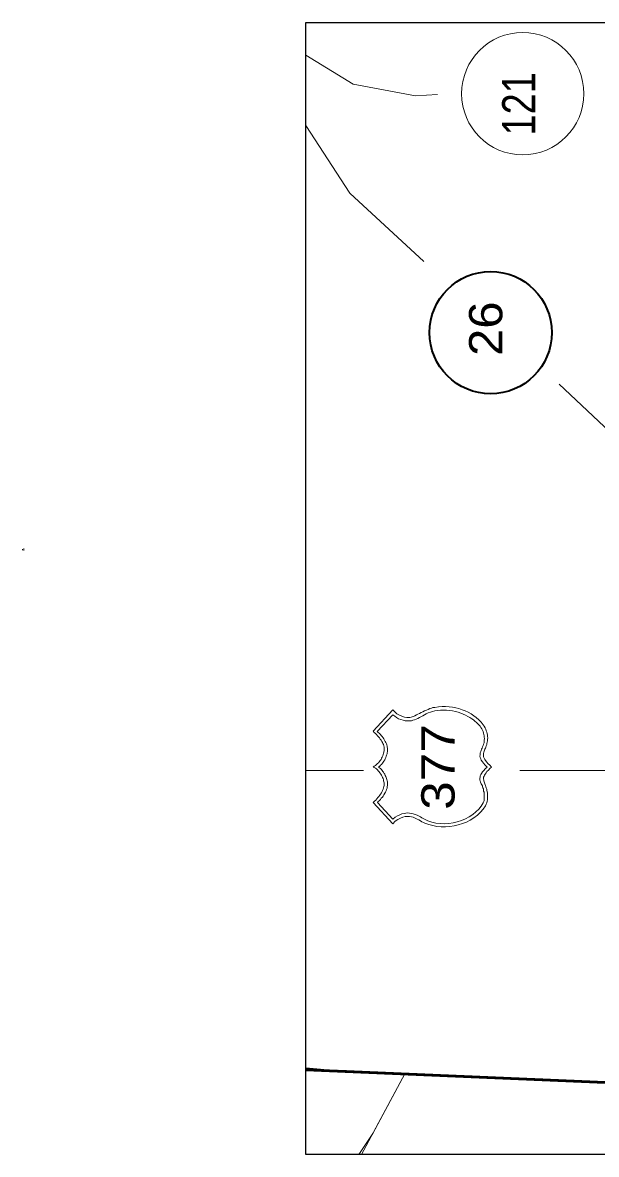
# Model space of a CAD drawing. Extents: x 2363323 to 2367082, y 6956018 to 6980837.
# Drawn here: x 2365163 to 2365427, y 6956018 to 6956538 of the extents above; entities that cross this region are included whole.
import ezdxf

# ---------------------------------------------------------------- set-up
doc = ezdxf.new("R2010")
doc.units = 0
doc.header["$LTSCALE"] = 4.1
for name, color, linetype, lineweight in [('61', 7, 'Continuous', 40), ('62', 7, 'Continuous', 13), ('63', 7, 'Continuous', 13)]:
    doc.layers.add(name, color=color, linetype=linetype, lineweight=lineweight)

msp = doc.modelspace()

# ---------------------------------------------------------------- linework, layer by layer
at = {"layer": '61', "lineweight": 25}
msp.add_lwpolyline([(2365293.134, 6956018.485), (2365293.134, 6956538.196), (2365958.89, 6956538.196), (2365958.89, 6956018.485)], close=True, dxfattribs=at)
at = {"layer": '62'}
for p, q in [((2365343.609, 6956504.644), (2365353.697, 6956505.184)), ((2365293.134, 6956490.977), (2365313.365, 6956459.916)), ((2365313.365, 6956459.916), (2365347.481, 6956428.58)), ((2365446.841, 6956337.136), (2365409.581, 6956372.152)), ((2365163.018, 6956296.007), (2365163.019, 6956296.479)), ((2365163.648, 6956295.715), (2365163.649, 6956296.749)), ((2365319.657, 6956194.836), (2365293.137, 6956194.836)), ((2365566.921, 6956194.836), (2365391.497, 6956194.836)), ((2365318.801, 6956018.484), (2365338.665, 6956055.412)), ((2365317.489, 6956018.484), (2365323.993, 6956028.136))]:
    msp.add_line(p, q, dxfattribs=at)
at = {"layer": '62', "lineweight": 25}
msp.add_line((2365308.229, 6956056.672), (2365293.137, 6956058.008), dxfattribs=at)
at = {"layer": '62'}
for points in [[(2365343.609, 6956504.644), (2365314.977, 6956509.956), (2365293.137, 6956523.332)], [(2365333.16, 6956170.305), (2365324.106, 6956180.094), (2365324.715, 6956180.634), (2365325.327, 6956181.171), (2365325.798, 6956181.783), (2365326.338, 6956182.323), (2365326.749, 6956182.863), (2365327.151, 6956183.475), (2365327.553, 6956183.946), (2365327.958, 6956184.555), (2365328.3, 6956185.095), (2365328.498, 6956185.635), (2365328.771, 6956186.241), (2365328.909, 6956186.781), (2365329.11, 6956187.387), (2365329.245, 6956187.861), (2365329.245, 6956188.473), (2365329.179, 6956189.076), (2365329.107, 6956189.487), (2365328.909, 6956189.955), (2365328.837, 6956190.495), (2365328.699, 6956191.035), (2365328.429, 6956191.575), (2365328.228, 6956192.046), (2365327.958, 6956192.586), (2365327.688, 6956193.129), (2365327.283, 6956193.666), (2365326.947, 6956194.137), (2365326.473, 6956194.611), (2365326.209, 6956195.088), (2365325.669, 6956195.487), (2365325.186, 6956195.826), (2365324.646, 6956196.096), (2365324.109, 6956196.369), (2365324.646, 6956196.708), (2365325.186, 6956197.107), (2365325.735, 6956197.446), (2365326.203, 6956197.917), (2365326.677, 6956198.319), (2365327.013, 6956198.868), (2365327.418, 6956199.336), (2365327.76, 6956199.879), (2365328.021, 6956200.416), (2365328.363, 6956200.956), (2365328.567, 6956201.565), (2365328.771, 6956202.105), (2365328.903, 6956202.783), (2365329.107, 6956203.257), (2365329.245, 6956203.929), (2365329.245, 6956204.538), (2365329.245, 6956205.006), (2365329.245, 6956205.546), (2365329.041, 6956206.017), (2365328.903, 6956206.626), (2365328.627, 6956207.097), (2365328.429, 6956207.643), (2365328.093, 6956208.117), (2365327.823, 6956208.651), (2365327.418, 6956209.128), (2365327.013, 6956209.737), (2365326.608, 6956210.208), (2365326.203, 6956210.748), (2365325.663, 6956211.219), (2365325.186, 6956211.828), (2365324.649, 6956212.227), (2365324.109, 6956212.773), (2365333.16, 6956222.565), (2365334.042, 6956221.683), (2365335.053, 6956220.807), (2365336.199, 6956220.198), (2365337.351, 6956219.727), (2365338.491, 6956219.253), (2365339.571, 6956219.118), (2365340.45, 6956219.049), (2365341.059, 6956219.118), (2365341.599, 6956219.19), (2365342.142, 6956219.457), (2365342.745, 6956219.589), (2365343.351, 6956219.928), (2365344.032, 6956220.267), (2365344.701, 6956220.603), (2365345.451, 6956220.939), (2365346.261, 6956221.347), (2365347.002, 6956221.749), (2365347.74, 6956222.151), (2365348.619, 6956222.493), (2365349.36, 6956222.829), (2365350.17, 6956223.168), (2365350.911, 6956223.375), (2365351.655, 6956223.639), (2365352.465, 6956223.705), (2365354.157, 6956223.975), (2365355.84, 6956224.113), (2365357.391, 6956224.113), (2365359.011, 6956223.978), (2365360.571, 6956223.843), (2365362.119, 6956223.507), (2365363.601, 6956223.168), (2365365.092, 6956222.697), (2365366.505, 6956222.157), (2365367.861, 6956221.479)], [(2365370.222, 6956217.969), (2365369.475, 6956218.509), (2365368.602, 6956219.118), (2365367.651, 6956219.589), (2365366.64, 6956220.129), (2365365.56, 6956220.609), (2365364.417, 6956221.077), (2365363.202, 6956221.548), (2365361.987, 6956221.887), (2365360.631, 6956222.16), (2365359.281, 6956222.358), (2365357.931, 6956222.493), (2365356.515, 6956222.493), (2365355.03, 6956222.43), (2365353.752, 6956222.289), (2365352.537, 6956222.157), (2365351.451, 6956221.887), (2365350.443, 6956221.548), (2365349.495, 6956221.209), (2365348.55, 6956220.807), (2365347.74, 6956220.399), (2365346.93, 6956219.928), (2365346.123, 6956219.46), (2365345.382, 6956219.118), (2365344.641, 6956218.713), (2365343.897, 6956218.377), (2365343.15, 6956218.038), (2365342.409, 6956217.837), (2365341.737, 6956217.633), (2365340.927, 6956217.501), (2365339.979, 6956217.498), (2365338.899, 6956217.639), (2365337.885, 6956217.837), (2365336.871, 6956218.11), (2365335.863, 6956218.509), (2365334.921, 6956219.118), (2365334.042, 6956219.727), (2365333.16, 6956220.399), (2365326.005, 6956212.71), (2365326.473, 6956212.227), (2365326.947, 6956211.831), (2365327.487, 6956211.357), (2365327.889, 6956210.883), (2365328.297, 6956210.343), (2365328.705, 6956209.803), (2365329.038, 6956209.263), (2365329.38, 6956208.717), (2365329.653, 6956208.111), (2365329.989, 6956207.571), (2365330.262, 6956206.965), (2365330.391, 6956206.491), (2365330.532, 6956205.885), (2365330.601, 6956205.411), (2365330.73, 6956205.006), (2365330.73, 6956204.529), (2365330.73, 6956204.061), (2365330.667, 6956203.455), (2365330.595, 6956202.915), (2365330.529, 6956202.375), (2365330.325, 6956201.766), (2365330.121, 6956201.298), (2365329.923, 6956200.686), (2365329.653, 6956200.149), (2365329.449, 6956199.675), (2365329.11, 6956198.997), (2365328.771, 6956198.598), (2365328.429, 6956198.121), (2365328.027, 6956197.587), (2365327.553, 6956197.248), (2365327.151, 6956196.771), (2365326.545, 6956196.363), (2365327.079, 6956195.955), (2365327.553, 6956195.625), (2365327.958, 6956195.151), (2365328.297, 6956194.746), (2365328.633, 6956194.347), (2365328.903, 6956193.939), (2365329.245, 6956193.396), (2365329.581, 6956193.057), (2365329.722, 6956192.517), (2365329.989, 6956192.046), (2365330.121, 6956191.578), (2365330.331, 6956191.107), (2365330.391, 6956190.624), (2365330.601, 6956190.087), (2365330.667, 6956189.613), (2365330.73, 6956189.145), (2365330.799, 6956188.605), (2365330.802, 6956187.927), (2365330.661, 6956187.384), (2365330.529, 6956186.715), (2365330.325, 6956186.106), (2365330.055, 6956185.431), (2365329.791, 6956184.756), (2365329.452, 6956184.285), (2365329.107, 6956183.607), (2365328.771, 6956183.001), (2365328.369, 6956182.452), (2365327.895, 6956181.984), (2365327.49, 6956181.375), (2365326.95, 6956180.904)], [(2365367.861, 6956221.479), (2365369.142, 6956220.738), (2365370.357, 6956219.928), (2365371.569, 6956219.049), (2365372.721, 6956217.966), (2365373.729, 6956216.889), (2365374.74, 6956215.743), (2365375.217, 6956215.068), (2365375.619, 6956214.399), (2365375.955, 6956213.718), (2365376.162, 6956213.043), (2365376.429, 6956212.437), (2365376.567, 6956211.759), (2365376.699, 6956211.018), (2365376.771, 6956210.409), (2365376.831, 6956209.74), (2365376.765, 6956209.065), (2365376.765, 6956208.447), (2365376.63, 6956207.841), (2365376.429, 6956207.166), (2365376.363, 6956206.626), (2365376.162, 6956206.086), (2365375.955, 6956205.549), (2365375.751, 6956205.006), (2365375.553, 6956204.535), (2365375.28, 6956204.061), (2365375.145, 6956203.593), (2365375.01, 6956203.116), (2365374.875, 6956202.576), (2365374.809, 6956202.108), (2365374.809, 6956201.565), (2365374.941, 6956201.028), (2365375.145, 6956200.485), (2365375.481, 6956199.876), (2365375.823, 6956199.336), (2365376.363, 6956198.595), (2365376.9, 6956197.917), (2365377.713, 6956197.245), (2365378.589, 6956196.366), (2365377.779, 6956195.628), (2365377.101, 6956194.881), (2365376.429, 6956194.275), (2365376.021, 6956193.666), (2365375.619, 6956193.129), (2365375.283, 6956192.583), (2365375.145, 6956192.115), (2365374.941, 6956191.641), (2365374.881, 6956191.236), (2365374.881, 6956190.768), (2365374.947, 6956190.426), (2365375.079, 6956189.955), (2365375.151, 6956189.547), (2365375.28, 6956189.145), (2365375.481, 6956188.671), (2365375.619, 6956188.203), (2365375.823, 6956187.861), (2365375.961, 6956187.321), (2365376.159, 6956186.781), (2365376.36, 6956186.241), (2365376.429, 6956185.635), (2365376.567, 6956185.095), (2365376.699, 6956184.423), (2365376.771, 6956183.883), (2365376.771, 6956183.199), (2365376.771, 6956182.665), (2365376.765, 6956181.984), (2365376.702, 6956181.246), (2365376.501, 6956180.637), (2365376.36, 6956179.965), (2365376.093, 6956179.287), (2365375.751, 6956178.609), (2365374.74, 6956177.055), (2365373.453, 6956175.573), (2365372.04, 6956174.223), (2365370.492, 6956173.011), (2365368.8, 6956171.925), (2365367.111, 6956171.055), (2365365.227, 6956170.374), (2365363.265, 6956169.771), (2365361.381, 6956169.363), (2365359.419, 6956169.024), (2365357.391, 6956168.889), (2365355.435, 6956168.889), (2365353.41, 6956169.093), (2365351.589, 6956169.435), (2365349.693, 6956169.969), (2365347.941, 6956170.644), (2365347.272, 6956170.914), (2365346.591, 6956171.253), (2365345.853, 6956171.655), (2365345.112, 6956172.129), (2365344.302, 6956172.471), (2365343.489, 6956172.873), (2365342.61, 6956173.275), (2365341.731, 6956173.413), (2365340.792, 6956173.614), (2365339.775, 6956173.614), (2365338.833, 6956173.614), (2365337.753, 6956173.275), (2365336.67, 6956172.939), (2365335.461, 6956172.267)], [(2365326.068, 6956180.094), (2365333.16, 6956172.405), (2365334.312, 6956173.275), (2365335.392, 6956173.881), (2365336.403, 6956174.424), (2365337.345, 6956174.829), (2365338.362, 6956175.036), (2365339.235, 6956175.231), (2365340.045, 6956175.369), (2365340.921, 6956175.237), (2365341.8, 6956175.033), (2365342.61, 6956174.895), (2365343.492, 6956174.625), (2365344.302, 6956174.223), (2365345.043, 6956173.884), (2365345.85, 6956173.479), (2365346.591, 6956173.005), (2365347.401, 6956172.534), (2365349.225, 6956171.655), (2365351.121, 6956171.049), (2365352.939, 6956170.575), (2365354.901, 6956170.377), (2365356.92, 6956170.305), (2365358.951, 6956170.374), (2365360.907, 6956170.713), (2365362.788, 6956171.184), (2365364.75, 6956171.793), (2365366.571, 6956172.606), (2365368.332, 6956173.479), (2365369.952, 6956174.559), (2365371.299, 6956175.705), (2365372.715, 6956176.989), (2365373.795, 6956178.405), (2365374.74, 6956179.893), (2365374.809, 6956180.235), (2365375.01, 6956180.571), (2365375.145, 6956181.039), (2365375.145, 6956181.579), (2365375.145, 6956181.987), (2365375.211, 6956182.527), (2365375.211, 6956183.064), (2365375.145, 6956183.607), (2365375.145, 6956184.216), (2365375.145, 6956184.756), (2365374.941, 6956185.299), (2365374.875, 6956185.839), (2365374.809, 6956186.379), (2365374.605, 6956186.847), (2365374.47, 6956187.315), (2365374.341, 6956187.729), (2365374.065, 6956188.203), (2365373.867, 6956188.605), (2365373.66, 6956189.007), (2365373.531, 6956189.415), (2365373.321, 6956189.958), (2365373.255, 6956190.291), (2365373.192, 6956190.765), (2365373.189, 6956191.236), (2365373.261, 6956191.704), (2365373.39, 6956192.385), (2365373.591, 6956192.856), (2365373.999, 6956193.396), (2365374.335, 6956194.077), (2365375.01, 6956194.746), (2365375.685, 6956195.556), (2365376.567, 6956196.303), (2365375.622, 6956197.245), (2365374.941, 6956198.055), (2365374.335, 6956198.727), (2365373.867, 6956199.477), (2365373.597, 6956200.146), (2365373.39, 6956200.686), (2365373.255, 6956201.298), (2365373.261, 6956201.901), (2365373.321, 6956202.441), (2365373.39, 6956202.915), (2365373.597, 6956203.455), (2365373.795, 6956203.989), (2365373.993, 6956204.535), (2365374.269, 6956205.006), (2365374.473, 6956205.615), (2365374.743, 6956206.221), (2365374.875, 6956206.827), (2365375.151, 6956207.439), (2365375.151, 6956208.111), (2365375.217, 6956208.717), (2365375.28, 6956209.398), (2365375.217, 6956210.073), (2365375.151, 6956210.679), (2365375.079, 6956211.357), (2365374.881, 6956211.963), (2365374.74, 6956212.638), (2365374.335, 6956213.241), (2365374.065, 6956213.925), (2365373.66, 6956214.459), (2365373.261, 6956215.137), (2365372.721, 6956215.743), (2365372.175, 6956216.349), (2365371.635, 6956216.823), (2365370.888, 6956217.363), (2365370.222, 6956217.969)], [(2365326.95, 6956180.904), (2365326.473, 6956180.499), (2365326.068, 6956180.094)], [(2365335.461, 6956172.267), (2365334.309, 6956171.454), (2365333.16, 6956170.305)]]:
    msp.add_lwpolyline(points, dxfattribs=at)
at = {"layer": '62', "lineweight": 53}
msp.add_lwpolyline([(2365293.137, 6956057.312), (2365488.705, 6956049.028), (2365530.289, 6956056.396)], dxfattribs=at)
at = {"layer": '62'}
msp.add_circle((2365392.892, 6956505.564), 28.094, dxfattribs=at)
at = {"layer": '62', "lineweight": 35}
msp.add_circle((2365378.16, 6956395.847), 28.094, dxfattribs=at)
at = {"layer": '63'}
for p, q in [((2365343.609, 6956504.644), (2365314.977, 6956509.956)), ((2365343.609, 6956504.644), (2365353.697, 6956505.184)), ((2365313.365, 6956459.916), (2365347.481, 6956428.58)), ((2365446.841, 6956337.136), (2365409.581, 6956372.152)), ((2365163.018, 6956296.007), (2365163.019, 6956296.479)), ((2365163.648, 6956295.715), (2365163.649, 6956296.749)), ((2365319.657, 6956194.836), (2365293.137, 6956194.836)), ((2365566.921, 6956194.836), (2365391.497, 6956194.836))]:
    msp.add_line(p, q, dxfattribs=at)
at = {"layer": '63', "lineweight": 25}
msp.add_line((2365308.229, 6956056.672), (2365293.137, 6956058.008), dxfattribs=at)
at = {"layer": '63'}
for points in [[(2365333.16, 6956170.305), (2365324.106, 6956180.094), (2365324.715, 6956180.634), (2365325.327, 6956181.171), (2365325.798, 6956181.783), (2365326.338, 6956182.323), (2365326.749, 6956182.863), (2365327.151, 6956183.475), (2365327.553, 6956183.946), (2365327.958, 6956184.555), (2365328.3, 6956185.095), (2365328.498, 6956185.635), (2365328.771, 6956186.241), (2365328.909, 6956186.781), (2365329.11, 6956187.387), (2365329.245, 6956187.861), (2365329.245, 6956188.473), (2365329.179, 6956189.076), (2365329.107, 6956189.487), (2365328.909, 6956189.955), (2365328.837, 6956190.495), (2365328.699, 6956191.035), (2365328.429, 6956191.575), (2365328.228, 6956192.046), (2365327.958, 6956192.586), (2365327.688, 6956193.129), (2365327.283, 6956193.666), (2365326.947, 6956194.137), (2365326.473, 6956194.611), (2365326.209, 6956195.088), (2365325.669, 6956195.487), (2365325.186, 6956195.826), (2365324.646, 6956196.096), (2365324.109, 6956196.369), (2365324.646, 6956196.708), (2365325.186, 6956197.107), (2365325.735, 6956197.446), (2365326.203, 6956197.917), (2365326.677, 6956198.319), (2365327.013, 6956198.868), (2365327.418, 6956199.336), (2365327.76, 6956199.879), (2365328.021, 6956200.416), (2365328.363, 6956200.956), (2365328.567, 6956201.565), (2365328.771, 6956202.105), (2365328.903, 6956202.783), (2365329.107, 6956203.257), (2365329.245, 6956203.929), (2365329.245, 6956204.538), (2365329.245, 6956205.006), (2365329.245, 6956205.546), (2365329.041, 6956206.017), (2365328.903, 6956206.626), (2365328.627, 6956207.097), (2365328.429, 6956207.643), (2365328.093, 6956208.117), (2365327.823, 6956208.651), (2365327.418, 6956209.128), (2365327.013, 6956209.737), (2365326.608, 6956210.208), (2365326.203, 6956210.748), (2365325.663, 6956211.219), (2365325.186, 6956211.828), (2365324.649, 6956212.227), (2365324.109, 6956212.773), (2365333.16, 6956222.565), (2365334.042, 6956221.683), (2365335.053, 6956220.807), (2365336.199, 6956220.198), (2365337.351, 6956219.727), (2365338.491, 6956219.253), (2365339.571, 6956219.118), (2365340.45, 6956219.049), (2365341.059, 6956219.118), (2365341.599, 6956219.19), (2365342.142, 6956219.457), (2365342.745, 6956219.589), (2365343.351, 6956219.928), (2365344.032, 6956220.267), (2365344.701, 6956220.603), (2365345.451, 6956220.939), (2365346.261, 6956221.347), (2365347.002, 6956221.749), (2365347.74, 6956222.151), (2365348.619, 6956222.493), (2365349.36, 6956222.829), (2365350.17, 6956223.168), (2365350.911, 6956223.375), (2365351.655, 6956223.639), (2365352.465, 6956223.705), (2365354.157, 6956223.975), (2365355.84, 6956224.113), (2365357.391, 6956224.113), (2365359.011, 6956223.978), (2365360.571, 6956223.843), (2365362.119, 6956223.507), (2365363.601, 6956223.168), (2365365.092, 6956222.697), (2365366.505, 6956222.157), (2365367.861, 6956221.479)], [(2365370.222, 6956217.969), (2365369.475, 6956218.509), (2365368.602, 6956219.118), (2365367.651, 6956219.589), (2365366.64, 6956220.129), (2365365.56, 6956220.609), (2365364.417, 6956221.077), (2365363.202, 6956221.548), (2365361.987, 6956221.887), (2365360.631, 6956222.16), (2365359.281, 6956222.358), (2365357.931, 6956222.493), (2365356.515, 6956222.493), (2365355.03, 6956222.43), (2365353.752, 6956222.289), (2365352.537, 6956222.157), (2365351.451, 6956221.887), (2365350.443, 6956221.548), (2365349.495, 6956221.209), (2365348.55, 6956220.807), (2365347.74, 6956220.399), (2365346.93, 6956219.928), (2365346.123, 6956219.46), (2365345.382, 6956219.118), (2365344.641, 6956218.713), (2365343.897, 6956218.377), (2365343.15, 6956218.038), (2365342.409, 6956217.837), (2365341.737, 6956217.633), (2365340.927, 6956217.501), (2365339.979, 6956217.498), (2365338.899, 6956217.639), (2365337.885, 6956217.837), (2365336.871, 6956218.11), (2365335.863, 6956218.509), (2365334.921, 6956219.118), (2365334.042, 6956219.727), (2365333.16, 6956220.399), (2365326.005, 6956212.71), (2365326.473, 6956212.227), (2365326.947, 6956211.831), (2365327.487, 6956211.357), (2365327.889, 6956210.883), (2365328.297, 6956210.343), (2365328.705, 6956209.803), (2365329.038, 6956209.263), (2365329.38, 6956208.717), (2365329.653, 6956208.111), (2365329.989, 6956207.571), (2365330.262, 6956206.965), (2365330.391, 6956206.491), (2365330.532, 6956205.885), (2365330.601, 6956205.411), (2365330.73, 6956205.006), (2365330.73, 6956204.529), (2365330.73, 6956204.061), (2365330.667, 6956203.455), (2365330.595, 6956202.915), (2365330.529, 6956202.375), (2365330.325, 6956201.766), (2365330.121, 6956201.298), (2365329.923, 6956200.686), (2365329.653, 6956200.149), (2365329.449, 6956199.675), (2365329.11, 6956198.997), (2365328.771, 6956198.598), (2365328.429, 6956198.121), (2365328.027, 6956197.587), (2365327.553, 6956197.248), (2365327.151, 6956196.771), (2365326.545, 6956196.363), (2365327.079, 6956195.955), (2365327.553, 6956195.625), (2365327.958, 6956195.151), (2365328.297, 6956194.746), (2365328.633, 6956194.347), (2365328.903, 6956193.939), (2365329.245, 6956193.396), (2365329.581, 6956193.057), (2365329.722, 6956192.517), (2365329.989, 6956192.046), (2365330.121, 6956191.578), (2365330.331, 6956191.107), (2365330.391, 6956190.624), (2365330.601, 6956190.087), (2365330.667, 6956189.613), (2365330.73, 6956189.145), (2365330.799, 6956188.605), (2365330.802, 6956187.927), (2365330.661, 6956187.384), (2365330.529, 6956186.715), (2365330.325, 6956186.106), (2365330.055, 6956185.431), (2365329.791, 6956184.756), (2365329.452, 6956184.285), (2365329.107, 6956183.607), (2365328.771, 6956183.001), (2365328.369, 6956182.452), (2365327.895, 6956181.984), (2365327.49, 6956181.375), (2365326.95, 6956180.904)], [(2365367.861, 6956221.479), (2365369.142, 6956220.738), (2365370.357, 6956219.928), (2365371.569, 6956219.049), (2365372.721, 6956217.966), (2365373.729, 6956216.889), (2365374.74, 6956215.743), (2365375.217, 6956215.068), (2365375.619, 6956214.399), (2365375.955, 6956213.718), (2365376.162, 6956213.043), (2365376.429, 6956212.437), (2365376.567, 6956211.759), (2365376.699, 6956211.018), (2365376.771, 6956210.409), (2365376.831, 6956209.74), (2365376.765, 6956209.065), (2365376.765, 6956208.447), (2365376.63, 6956207.841), (2365376.429, 6956207.166), (2365376.363, 6956206.626), (2365376.162, 6956206.086), (2365375.955, 6956205.549), (2365375.751, 6956205.006), (2365375.553, 6956204.535), (2365375.28, 6956204.061), (2365375.145, 6956203.593), (2365375.01, 6956203.116), (2365374.875, 6956202.576), (2365374.809, 6956202.108), (2365374.809, 6956201.565), (2365374.941, 6956201.028), (2365375.145, 6956200.485), (2365375.481, 6956199.876), (2365375.823, 6956199.336), (2365376.363, 6956198.595), (2365376.9, 6956197.917), (2365377.713, 6956197.245), (2365378.589, 6956196.366), (2365377.779, 6956195.628), (2365377.101, 6956194.881), (2365376.429, 6956194.275), (2365376.021, 6956193.666), (2365375.619, 6956193.129), (2365375.283, 6956192.583), (2365375.145, 6956192.115), (2365374.941, 6956191.641), (2365374.881, 6956191.236), (2365374.881, 6956190.768), (2365374.947, 6956190.426), (2365375.079, 6956189.955), (2365375.151, 6956189.547), (2365375.28, 6956189.145), (2365375.481, 6956188.671), (2365375.619, 6956188.203), (2365375.823, 6956187.861), (2365375.961, 6956187.321), (2365376.159, 6956186.781), (2365376.36, 6956186.241), (2365376.429, 6956185.635), (2365376.567, 6956185.095), (2365376.699, 6956184.423), (2365376.771, 6956183.883), (2365376.771, 6956183.199), (2365376.771, 6956182.665), (2365376.765, 6956181.984), (2365376.702, 6956181.246), (2365376.501, 6956180.637), (2365376.36, 6956179.965), (2365376.093, 6956179.287), (2365375.751, 6956178.609), (2365374.74, 6956177.055), (2365373.453, 6956175.573), (2365372.04, 6956174.223), (2365370.492, 6956173.011), (2365368.8, 6956171.925), (2365367.111, 6956171.055), (2365365.227, 6956170.374), (2365363.265, 6956169.771), (2365361.381, 6956169.363), (2365359.419, 6956169.024), (2365357.391, 6956168.889), (2365355.435, 6956168.889), (2365353.41, 6956169.093), (2365351.589, 6956169.435), (2365349.693, 6956169.969), (2365347.941, 6956170.644), (2365347.272, 6956170.914), (2365346.591, 6956171.253), (2365345.853, 6956171.655), (2365345.112, 6956172.129), (2365344.302, 6956172.471), (2365343.489, 6956172.873), (2365342.61, 6956173.275), (2365341.731, 6956173.413), (2365340.792, 6956173.614), (2365339.775, 6956173.614), (2365338.833, 6956173.614), (2365337.753, 6956173.275), (2365336.67, 6956172.939), (2365335.461, 6956172.267)], [(2365326.068, 6956180.094), (2365333.16, 6956172.405), (2365334.312, 6956173.275), (2365335.392, 6956173.881), (2365336.403, 6956174.424), (2365337.345, 6956174.829), (2365338.362, 6956175.036), (2365339.235, 6956175.231), (2365340.045, 6956175.369), (2365340.921, 6956175.237), (2365341.8, 6956175.033), (2365342.61, 6956174.895), (2365343.492, 6956174.625), (2365344.302, 6956174.223), (2365345.043, 6956173.884), (2365345.85, 6956173.479), (2365346.591, 6956173.005), (2365347.401, 6956172.534), (2365349.225, 6956171.655), (2365351.121, 6956171.049), (2365352.939, 6956170.575), (2365354.901, 6956170.377), (2365356.92, 6956170.305), (2365358.951, 6956170.374), (2365360.907, 6956170.713), (2365362.788, 6956171.184), (2365364.75, 6956171.793), (2365366.571, 6956172.606), (2365368.332, 6956173.479), (2365369.952, 6956174.559), (2365371.299, 6956175.705), (2365372.715, 6956176.989), (2365373.795, 6956178.405), (2365374.74, 6956179.893), (2365374.809, 6956180.235), (2365375.01, 6956180.571), (2365375.145, 6956181.039), (2365375.145, 6956181.579), (2365375.145, 6956181.987), (2365375.211, 6956182.527), (2365375.211, 6956183.064), (2365375.145, 6956183.607), (2365375.145, 6956184.216), (2365375.145, 6956184.756), (2365374.941, 6956185.299), (2365374.875, 6956185.839), (2365374.809, 6956186.379), (2365374.605, 6956186.847), (2365374.47, 6956187.315), (2365374.341, 6956187.729), (2365374.065, 6956188.203), (2365373.867, 6956188.605), (2365373.66, 6956189.007), (2365373.531, 6956189.415), (2365373.321, 6956189.958), (2365373.255, 6956190.291), (2365373.192, 6956190.765), (2365373.189, 6956191.236), (2365373.261, 6956191.704), (2365373.39, 6956192.385), (2365373.591, 6956192.856), (2365373.999, 6956193.396), (2365374.335, 6956194.077), (2365375.01, 6956194.746), (2365375.685, 6956195.556), (2365376.567, 6956196.303), (2365375.622, 6956197.245), (2365374.941, 6956198.055), (2365374.335, 6956198.727), (2365373.867, 6956199.477), (2365373.597, 6956200.146), (2365373.39, 6956200.686), (2365373.255, 6956201.298), (2365373.261, 6956201.901), (2365373.321, 6956202.441), (2365373.39, 6956202.915), (2365373.597, 6956203.455), (2365373.795, 6956203.989), (2365373.993, 6956204.535), (2365374.269, 6956205.006), (2365374.473, 6956205.615), (2365374.743, 6956206.221), (2365374.875, 6956206.827), (2365375.151, 6956207.439), (2365375.151, 6956208.111), (2365375.217, 6956208.717), (2365375.28, 6956209.398), (2365375.217, 6956210.073), (2365375.151, 6956210.679), (2365375.079, 6956211.357), (2365374.881, 6956211.963), (2365374.74, 6956212.638), (2365374.335, 6956213.241), (2365374.065, 6956213.925), (2365373.66, 6956214.459), (2365373.261, 6956215.137), (2365372.721, 6956215.743), (2365372.175, 6956216.349), (2365371.635, 6956216.823), (2365370.888, 6956217.363), (2365370.222, 6956217.969)], [(2365326.95, 6956180.904), (2365326.473, 6956180.499), (2365326.068, 6956180.094)], [(2365335.461, 6956172.267), (2365334.309, 6956171.454), (2365333.16, 6956170.305)], [(2365317.489, 6956018.484), (2365323.993, 6956028.136), (2365338.665, 6956055.412)]]:
    msp.add_lwpolyline(points, dxfattribs=at)
at = {"layer": '63', "lineweight": 53}
msp.add_lwpolyline([(2365308.229, 6956056.672), (2365488.705, 6956049.028), (2365530.289, 6956056.396)], dxfattribs=at)
at = {"layer": '63'}
for centre in [(2365392.892, 6956505.564), (2365378.16, 6956395.847)]:
    msp.add_circle(centre, 28.094, dxfattribs=at)

# ---------------------------------------------------------------- texts
at = {"layer": '62'}
for s, height, width, p in [('121', 15.3, 0.85, (2365398.745, 6956486.392)), ('26', 15.3, 1.1, (2365383.52, 6956385.127)), ('377', 15.32, 1.15, (2365361.579, 6956176.719))]:
    msp.add_text(s, height=height, rotation=90, dxfattribs=dict(at, width=width)).set_placement(p)
at = {"layer": '63'}
for s, height, width, p in [('121', 15.3, 0.85, (2365398.745, 6956486.392)), ('26', 15.3, 1.1, (2365383.52, 6956385.127)), ('377', 15.32, 1.15, (2365361.579, 6956176.719))]:
    msp.add_text(s, height=height, rotation=90, dxfattribs=dict(at, width=width)).set_placement(p)

doc.saveas('drawing.dxf')
